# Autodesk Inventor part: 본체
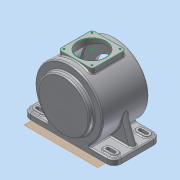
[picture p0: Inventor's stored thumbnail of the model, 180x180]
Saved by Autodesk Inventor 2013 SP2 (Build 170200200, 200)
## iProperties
Created: 2015-06
Part Number: 본체
Material: 알루미늄 6061
Document SubType Name: Modeling
Designer: dgall
Density: 2.71 g/cm^3
Mass: 3275.47 g
Surface Area: 2300.77 cm^2
Volume: 1208.66 cm^3
Author: dgall
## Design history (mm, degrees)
node "작업 평면1"
sketch "스케치9"
  geometry: L1 (-115, -59)-(115, -59); L2 (115, -59)-(115, 59); L3 (115, 59)-(-115, 59); L4 (-115, 59)-(-115, -59); L5 (-115, -59)-(115, 59); L6 (115, -59)-(-115, 59); 1 further point
  constraints: 12 end point, 2 midpoint, 2 parallel, 1 horizontal, 1 perpendicular
  dimensions: "d36" = 118 distance of L1.end L2.end; "d38" = 230 distance of L2.end L3.end
extrude "돌출9" join sketch "스케치9" distance "d39" = 14; taper "d40" = 0 deg
sketch "스케치1"
  geometry: C1 r 85 at (0, 0); 1 further point
  constraints: 1 centre point, 1 coincident
  dimensions: "d0" = 170 diameter of C1
extrude "돌출1" new body sketch "스케치1" stored distance "d2" = 118; taper "d3" = 0 deg
sketch "스케치2"
  geometry: C1 r 77 at (0, 0); 1 further point
  constraints: 1 centre point, 1 coincident
  dimensions: "d4" = 154 diameter of C1
extrude "돌출2" cut sketch "스케치2" stored distance "d6" = 102; taper "d7" = 0 deg
sketch "스케치3"
  geometry: C1 r 85 at (0, 0) reference; C2 r 65 at (0, 0)
  constraints: 1 centre point, 1 coincident
  dimensions: "d8" = 130 diameter of C2
extrude "돌출3" join sketch "스케치3" distance "d10" = 13; taper "d11" = 0 deg
sketch "스케치4"
  geometry: C1 r 85 at (0, 0) reference; C2 r 65 at (0, 0)
  constraints: 1 centre point, 1 coincident
  dimensions: "d12" = 130 diameter of C2
extrude "돌출4" join sketch "스케치4" distance "d15" = 3; taper "d16" = 0 deg
sketch "스케치5"
  geometry: C1 r 65 at (0, 0) reference; C2 r 47.5 at (0, 0)
  constraints: 1 centre point, 1 coincident
  dimensions: "d17" = 95 diameter of C2
extrude "돌출5" cut sketch "스케치5" stored distance "d19" = 3; taper "d20" = 0 deg
sketch "스케치6"
  geometry: C1 r 77 at (0, 0) reference; C2 r 31 at (0, 0)
  constraints: 1 centre point, 1 coincident
  dimensions: "d21" = 62 diameter of C2
extrude "돌출6" join sketch "스케치6" distance "d23" = 3.5; taper "d24" = 0 deg
feature "면 기울기1" dims angle "d25" = 25 deg
sketch "스케치7"
  geometry: C1 r 29.368 at (0, 0) reference; C2 r 23.5 at (0, 0)
  constraints: 1 centre point, 1 coincident
  dimensions: "d26" = 47 diameter of C2
extrude "돌출7" cut sketch "스케치7" distance "d29" = 14; taper "d30" = 0 deg
sketch "스케치8"
  geometry: C1 r 23.5 at (0, 0) reference; C2 r 15 at (0, 0)
  constraints: 1 centre point, 1 coincident
  dimensions: "d31" = 30 diameter of C2
extrude "돌출8" cut sketch "스케치8" distance "d33" = 3; taper "d34" = 0 deg
sketch "스케치10"
  geometry: L1 (81, 32)-(97, 32); L2 (97, 50)-(81, 50); A1 r 9 centre (97, 41) between (97, 32) and (97, 50); A2 r 9 centre (81, 41) between (81, 50) and (81, 32); 1 further point
  constraints: 4 end point, 4 point on circle, 4 tangent, 2 centre point, 1 horizontal alignment
  dimensions: "d44" = 18 diameter of A1; "d46" = 97 horizontal distance of point (0, 0) A1.centre; "d47" = 41 vertical distance of point (0, 0) A1.centre; "d48" = 18 diameter of A2; "d49" = 16 distance of A1.centre A2.centre
extrude "돌출10" join sketch "스케치10" distance "d50" = 3; taper "d51" = 0 deg
sketch "스케치11"
  geometry: L1 (81, 45)-(97, 45); L2 (97, 37)-(81, 37); A1 r 9 centre (97, 41) between (97, 32) and (97, 50) reference; A2 r 9 centre (81, 41) between (81, 50) and (81, 32) reference; A3 r 4 centre (97, 41) between (97, 37) and (97, 45); A4 r 4 centre (81, 41) between (81, 45) and (81, 37); 1 further point
  constraints: 4 end point, 4 point on circle, 4 tangent, 2 centre point, 2 coincident
  dimensions: "d52" = 8 diameter of A4; "d54" = 8 diameter of A3
extrude "돌출11" cut sketch "스케치11" stored distance "d55" = 3; taper "d56" = 0 deg
fillet "모깎기1" dims "d57" = 3
fillet "모깎기2" dims "d58" = 18
node "작업 평면2"
sketch "스케치12"
  geometry: L1 (-42.5, -42.5)-(42.5, -42.5); L2 (42.5, -42.5)-(42.5, 42.5); L3 (42.5, 42.5)-(-42.5, 42.5); L4 (-42.5, 42.5)-(-42.5, -42.5); L5 (-42.5, -42.5)-(42.5, 42.5); L6 (42.5, -42.5)-(-42.5, 42.5); 1 further point
  constraints: 12 end point, 2 midpoint, 2 parallel, 1 horizontal, 1 perpendicular
  dimensions: "d66" = 85 distance of L2.end L3.end; "d68" = 85 distance of L1.end L2.end
extrude "돌출12" join sketch "스케치12" stored distance "d69" = 3; taper "d70" = 0 deg
sketch "스케치13"
  geometry: C1 r 35 at (0, 0); 1 further point
  constraints: 1 centre point, 1 coincident
  dimensions: "d71" = 70 diameter of C1
extrude "돌출13" cut sketch "스케치13" stored distance "d73" = 3; taper "d74" = 0 deg
fillet "모깎기3" dims "d75" = 7
sketch "스케치14"
  geometry: L1 (-109, -71)-(-84.87, -4.703); L2 (-46.733, -71)-(-97, -71) reference; L3 (-115, -85)-(-115, -71) reference; L4 (-46.733, -71)-(-109, -71); A1 r 85 centre (0, 0) between (46.733, -71) and (-46.733, -71) reference; A2 r 85 centre (0, 0) between (-84.87, -4.703) and (-46.733, -71); 1 further point
  constraints: 4 end point, 3 point on circle, 1 centre point, 1 coincident, 1 collinear, 1 point on line
  dimensions: "d76" = 6 distance from line of L3 L1.start; "d77" = 70 deg angle of L2 L1
extrude "돌출14" join sketch "스케치14" stored distance "d78" = 15; taper "d79" = 0 deg
sketch "스케치15"
  geometry: L1 (0, 0)-(94.362, 44.002); L2 (46.733, -71)-(97, -71) reference
  constraints: 2 end point
  dimensions: "d80" = 25 deg angle of L2 L1
node "작업 평면3"
sketch "스케치16"
  geometry: 2 further points
  constraints: 1 coincident, 1 other
sketch "스케치17"
  geometry: L1 (-42.5, 35.5)-(-42.5, -35.5) reference; L2 (-35.5, -42.5)-(35.5, -42.5) reference; L3 (42.5, -35.5)-(42.5, 35.5) reference; L4 (35.5, 42.5)-(-35.5, 42.5) reference; C1 r 35 at (0, 0) reference; A1 r 7 centre (-35.5, 35.5) between (-35.5, 42.5) and (-42.5, 35.5) reference; A2 r 7 centre (-35.5, -35.5) between (-42.5, -35.5) and (-35.5, -42.5) reference; A3 r 7 centre (35.5, -35.5) between (35.5, -42.5) and (42.5, -35.5) reference; A4 r 7 centre (35.5, 35.5) between (42.5, 35.5) and (35.5, 42.5) reference
sketch "스케치18"
  geometry: L1 (0, -98.8)-(0, 88.8) reference; L2 (-161, 0)-(161, 0) reference; A1 r 7 centre (-35.5, -35.5) between (-42.5, -35.5) and (-35.5, -42.5) reference; 4 further points
  constraints: 1 coincident
  dimensions: "d81" = 71 distance of point (35.5, -35.5) point (35.5, 35.5); "d83" = 71 distance of point (35.5, 35.5) point (-35.5, 35.5); "d84" = 35.5 distance from line of point (35.5, 35.5) L1; "d85" = 35.5 distance from line of L2 point (35.5, 35.5); "d86" = 71 distance of point (-35.5, -35.5) point (35.5, -35.5); "d87" = 71 distance of point (-35.5, 35.5) point (-35.5, -35.5)
hole "구멍1" sketch "스케치18" at (35.5, -35.5) diameter "d88" = 3.242; stored, may be unused: countersink angle "d92" = 82 deg, drill point angle "d94" = 118 deg; dims "d89" = 10, "d90" = 3.023, "d91" = 2, "d93" = 13
sketch "스케치19"
  geometry: C1 r 47.5 at (0, 0) reference; 1 further point
  dimensions: "d101" = 55 distance of C1.centre point (0, 55)
hole "구멍2" sketch "스케치19" at (0, 55) diameter "d102" = 3.242; stored, may be unused: countersink angle "d106" = 82 deg, drill point angle "d108" = 118 deg; dims "d103" = 10, "d104" = 3.023, "d105" = 2, "d107" = 13
fillet "모깎기4" dims "d112" = 7.5
chamfer "모따기1" distance "d113" = 1; stored, may be unused: second distance "d114" = 2, angle "d115" = 45 deg
fillet "모깎기6" dims "d117" = 3
fillet "모깎기8" dims "d119" = 3
feature "엠보싱2" dims "d12" = 130, "d122" = 0.5, "d123" = 0
fillet "모깎기9" dims "d124" = 3
fillet "모깎기10" dims "d125" = 3
fillet "모깎기11" dims "d126" = 3
fillet "모깎기12" dims "d127" = 3
fillet "모깎기13" dims "d128" = 0.3
chamfer "모따기2" distance "d129" = 1; stored, may be unused: second distance "d130" = 2, angle "d131" = 45 deg
fillet "모깎기14" dims "d132" = 3
fillet "모깎기15" dims "d133" = 3
node "솔리드1"
pattern_linear "직사각형 패턴1" dims "d61" = 178, "d64" = 82
mirror "대칭1"
pattern_linear "직사각형 패턴2" dims "d97" = 71, "d100" = 71
pattern_circular "원형 패턴1" dims angle "d110" = 360 deg
other parameters: "d35" = -85, "d65" = 173
